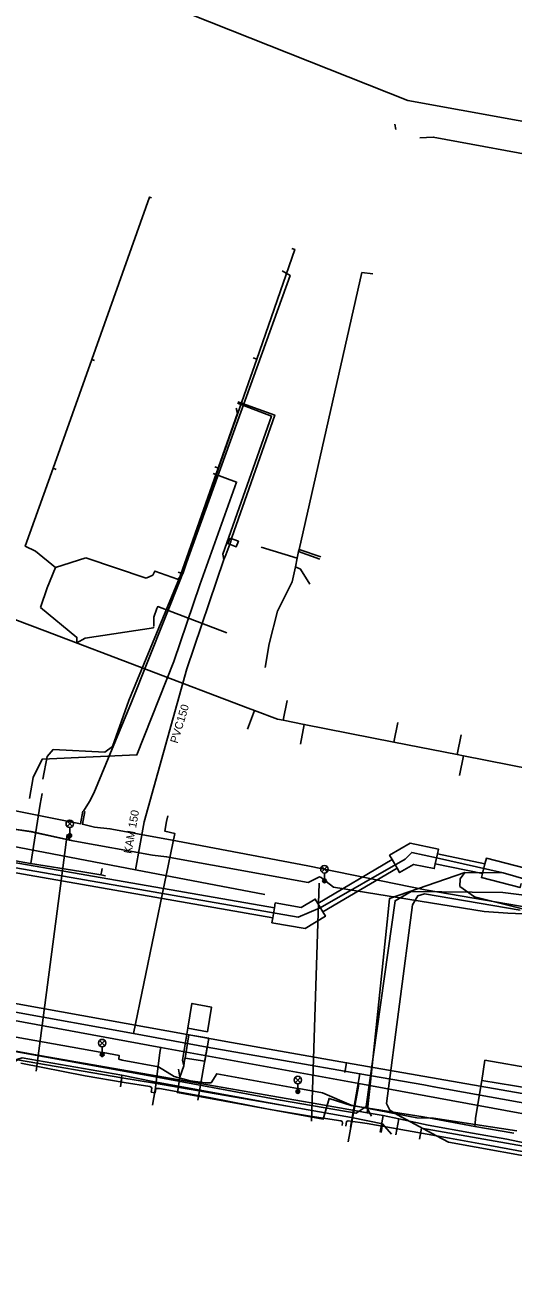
# Model space of a CAD drawing. Extents: x -596228 to -595156, y -1161235 to -1159373.
# Drawn here: x -595977.9 to -595929.1, y -1160338.7 to -1160214.5 of the extents above; entities that cross this region are included whole.
import ezdxf

# ---------------------------------------------------------------- set-up
doc = ezdxf.new("R2010")
doc.units = 0
for name, color, linetype in [('Vrstva 1', 7, 'Continuous'), ('Vrstva 10', 7, 'Continuous'), ('Vrstva 12', 7, 'Continuous'), ('Vrstva 13', 7, 'Continuous'), ('Vrstva 14', 7, 'Continuous'), ('Vrstva 16', 7, 'Continuous'), ('Vrstva 33', 7, 'Continuous'), ('Vrstva 42', 7, 'Continuous'), ('Vrstva 5', 7, 'Continuous'), ('Vrstva 54', 7, 'Continuous'), ('Vrstva 55', 7, 'Continuous'), ('Vrstva 58', 7, 'Continuous'), ('Vrstva 8', 7, 'Continuous'), ('Vrstva 9', 7, 'Continuous')]:
    doc.layers.add(name, color=color, linetype=linetype)

msp = doc.modelspace()

# ---------------------------------------------------------------- linework, layer by layer
at = {"layer": 'Vrstva 1'}
for p, q in [((-595940.938, -1160224.416), (-595940.817, -1160224.964)), ((-595940.938, -1160224.416), (-595940.817, -1160224.964)), ((-595940.938, -1160224.416), (-595940.817, -1160224.964)), ((-595965.453, -1160231.707), (-595965.257, -1160231.788)), ((-595944.225, -1160239.242), (-595950.502, -1160266.906)), ((-595943.129, -1160239.366), (-595944.225, -1160239.242)), ((-595970.953, -1160248.023), (-595971.225, -1160247.927)), ((-595955.08, -1160247.774), (-595954.732, -1160247.91)), ((-595974.774, -1160258.917), (-595975.096, -1160258.804)), ((-595958.907, -1160258.671), (-595958.552, -1160258.79)), ((-595974.851, -1160268.702), (-595976.86, -1160267.085)), ((-595954.288, -1160266.702), (-595950.691, -1160267.797)), ((-595948.335, -1160267.637), (-595950.502, -1160266.906)), ((-595974.851, -1160268.702), (-595971.799, -1160267.755)), ((-595971.799, -1160267.755), (-595965.797, -1160269.776)), ((-595948.413, -1160267.881), (-595950.551, -1160267.132)), ((-595975.683, -1160270.766), (-595974.851, -1160268.702)), ((-595965.797, -1160269.776), (-595965.117, -1160269.499)), ((-595965.117, -1160269.499), (-595964.958, -1160269.155)), ((-595962.598, -1160269.183), (-595962.133, -1160269.335)), ((-595976.35, -1160272.725), (-595975.683, -1160270.766)), ((-595951.191, -1160270.155), (-595952.648, -1160273.078)), ((-595965.013, -1160273.678), (-595964.708, -1160272.831)), ((-595952.648, -1160273.078), (-595953.493, -1160276.354)), ((-595965.017, -1160274.589), (-595965.013, -1160273.678)), ((-595965.037, -1160274.65), (-595965.065, -1160274.732)), ((-595953.493, -1160276.354), (-595953.879, -1160278.709)), ((-595955.666, -1160284.865), (-595954.957, -1160282.995)), ((-595951.692, -1160282.021), (-595952.078, -1160283.983)), ((-595950.375, -1160286.356), (-595949.988, -1160284.394)), ((-595940.634, -1160284.199), (-595941.02, -1160286.161)), ((-595934.315, -1160285.443), (-595934.702, -1160287.405)), ((-595934.45, -1160289.493), (-595934.064, -1160287.531))]:
    msp.add_line(p, q, dxfattribs=at)
for points in [[(-595912.502, -1160230.231), (-595937.093, -1160225.712), (-595938.437, -1160225.792)], [(-595976.86, -1160267.085), (-595977.87, -1160266.599), (-595975.096, -1160258.804), (-595971.225, -1160247.927), (-595965.453, -1160231.707), (-595965.257, -1160231.788)], [(-595964.958, -1160269.155), (-595964.919, -1160269.071), (-595962.659, -1160269.89), (-595962.133, -1160269.335), (-595958.552, -1160258.79), (-595954.732, -1160247.91), (-595950.936, -1160236.932), (-595951.239, -1160236.837)], [(-595956.671, -1160252.305), (-595953.26, -1160253.581), (-595958.13, -1160267.386), (-595958.022, -1160267.926)], [(-595952.65, -1160283.87), (-595954.957, -1160282.995), (-595955.58, -1160282.758), (-595975.9, -1160275.05), (-595978.902, -1160273.911), (-595985.549, -1160271.389), (-595989.355, -1160269.945), (-595993.328, -1160268.438), (-595993.749, -1160268.278), (-595994.45, -1160268.012), (-595998.91, -1160266.32)], [(-595950.502, -1160266.906), (-595950.551, -1160267.132), (-595950.691, -1160267.797), (-595950.874, -1160268.658), (-595951.191, -1160270.155)], [(-595949.415, -1160270.376), (-595950.349, -1160268.887), (-595950.874, -1160268.658)], [(-595976.35, -1160272.725), (-595972.702, -1160275.701), (-595972.715, -1160276.258)], [(-595964.708, -1160272.831), (-595964.621, -1160272.632), (-595957.729, -1160275.25)], [(-595965.065, -1160274.732), (-595971.872, -1160275.766), (-595972.715, -1160276.258)], [(-595909.29, -1160292.41), (-595911.144, -1160292.045), (-595918.081, -1160290.678), (-595918.179, -1160290.659), (-595934.064, -1160287.531), (-595934.702, -1160287.405), (-595941.02, -1160286.161), (-595949.988, -1160284.394), (-595952.078, -1160283.983), (-595952.65, -1160283.87)]]:
    msp.add_lwpolyline(points, dxfattribs=at)
at = {"layer": 'Vrstva 10'}
for p, q in [((-596048.34, -1160286.09), (-595952.97, -1160302.73)), ((-596048.34, -1160286.09), (-595952.97, -1160302.73)), ((-596048.51, -1160287.07), (-595953.14, -1160303.72)), ((-596048.51, -1160287.07), (-595953.14, -1160303.72)), ((-595941.21, -1160297.9), (-595948.63, -1160302.28)), ((-595941.21, -1160297.9), (-595948.63, -1160302.28)), ((-595941.21, -1160297.9), (-595940.7, -1160298.76)), ((-595941.21, -1160297.9), (-595940.7, -1160298.76)), ((-595936.68, -1160297.34), (-595936.89, -1160298.32)), ((-595936.68, -1160297.34), (-595936.89, -1160298.32)), ((-595936.68, -1160297.34), (-595931.93, -1160298.34)), ((-595936.68, -1160297.34), (-595931.93, -1160298.34)), ((-595940.7, -1160298.76), (-595948.12, -1160303.14)), ((-595940.7, -1160298.76), (-595948.12, -1160303.14)), ((-595936.89, -1160298.32), (-595932.18, -1160299.31)), ((-595936.89, -1160298.32), (-595932.18, -1160299.31)), ((-595931.93, -1160298.34), (-595932.18, -1160299.31)), ((-595931.93, -1160298.34), (-595932.18, -1160299.31)), ((-595952.97, -1160302.73), (-595953.14, -1160303.72)), ((-595952.97, -1160302.73), (-595953.14, -1160303.72)), ((-595948.63, -1160302.28), (-595948.12, -1160303.14)), ((-595948.63, -1160302.28), (-595948.12, -1160303.14))]:
    msp.add_line(p, q, dxfattribs=at)
for points in [[(-595941.21, -1160297.9), (-595941.46, -1160297.47), (-595939.41, -1160296.26), (-595936.58, -1160296.85), (-595936.68, -1160297.34)], [(-595941.21, -1160297.9), (-595941.46, -1160297.47), (-595939.41, -1160296.26), (-595936.58, -1160296.85), (-595936.68, -1160297.34)], [(-595931.93, -1160298.34), (-595931.78, -1160297.77), (-595927.91, -1160298.77), (-595928.05, -1160299.31)], [(-595931.93, -1160298.34), (-595931.78, -1160297.77), (-595927.91, -1160298.77), (-595928.05, -1160299.31)], [(-595936.89, -1160298.32), (-595936.99, -1160298.81), (-595939.06, -1160298.38), (-595940.45, -1160299.2), (-595940.7, -1160298.76)], [(-595936.89, -1160298.32), (-595936.99, -1160298.81), (-595939.06, -1160298.38), (-595940.45, -1160299.2), (-595940.7, -1160298.76)], [(-595928.3, -1160300.28), (-595928.41, -1160300.71), (-595932.28, -1160299.7), (-595932.18, -1160299.31)], [(-595928.3, -1160300.28), (-595928.41, -1160300.71), (-595932.28, -1160299.7), (-595932.18, -1160299.31)], [(-595952.97, -1160302.73), (-595952.89, -1160302.24), (-595950.29, -1160302.68), (-595948.88, -1160301.85), (-595948.63, -1160302.28)], [(-595952.97, -1160302.73), (-595952.89, -1160302.24), (-595950.29, -1160302.68), (-595948.88, -1160301.85), (-595948.63, -1160302.28)], [(-595948.12, -1160303.14), (-595947.87, -1160303.57), (-595949.9, -1160304.78), (-595953.22, -1160304.21), (-595953.14, -1160303.72)], [(-595948.12, -1160303.14), (-595947.87, -1160303.57), (-595949.9, -1160304.78), (-595953.22, -1160304.21), (-595953.14, -1160303.72)]]:
    msp.add_lwpolyline(points, dxfattribs=at)
at = {"layer": 'Vrstva 12'}
for p, q in [((-595933.92, -1160299.18), (-595930.09, -1160299.24)), ((-595968.23, -1160319.71), (-595968.36, -1160320.6)), ((-595949.09, -1160322.25), (-595950.27, -1160322.04)), ((-595940.54, -1160323.82), (-595940.82, -1160325.42)), ((-595937.61, -1160324.46), (-595940.54, -1160323.82)), ((-595942.16, -1160324.31), (-595942.31, -1160325.16)), ((-595942.16, -1160324.31), (-595941.25, -1160325.35)), ((-595933.18, -1160325.24), (-595937.61, -1160324.46)), ((-595929.73, -1160325.84), (-595933.18, -1160325.24)), ((-595921.13, -1160327.66), (-595929.73, -1160325.84))]:
    msp.add_line(p, q, dxfattribs=at)
for points in [[(-595906.85, -1160231.25), (-595907.387, -1160230.78), (-595907.31, -1160230.14), (-595906.92, -1160227.97), (-595939.63, -1160222.04), (-595961.4, -1160213.41), (-595962.62, -1160212.93), (-595961.32, -1160205.66)], [(-596051.724, -1160286.477), (-596048.43, -1160286.58), (-595950.59, -1160303.65), (-595948.38, -1160302.71), (-595939.91, -1160297.86), (-595939.24, -1160297.19), (-595936.77, -1160297.74), (-595930.09, -1160299.24)], [(-595916.466, -1160292.479), (-595917.33, -1160296.71), (-595919.49, -1160301.3), (-595921.53, -1160302.54), (-595925, -1160302.02), (-595927.78, -1160302.93), (-595932.98, -1160301.64), (-595934.44, -1160300.59), (-595934.41, -1160299.84), (-595933.92, -1160299.18)], [(-595933.92, -1160299.18), (-595941.47, -1160301.8), (-595941.61, -1160303.16), (-595943.46, -1160321.07), (-595943.68, -1160323.2)], [(-595930.09, -1160299.24), (-595889.94, -1160310.85), (-595809.314, -1160322.217)], [(-595993.27, -1160315.38), (-595985.71, -1160316.88), (-595979.31, -1160318.37), (-595978.65, -1160317.92), (-595968.23, -1160319.71)], [(-595950.27, -1160322.04), (-595977, -1160317.37), (-595992.24, -1160314.56)], [(-595968.23, -1160319.71), (-595965.16, -1160320.23), (-595951.67, -1160322.53), (-595945.25, -1160323.67), (-595942.16, -1160324.31)], [(-595943.68, -1160323.2), (-595944.97, -1160322.97), (-595949.09, -1160322.25)], [(-595940.54, -1160323.82), (-595942.11, -1160323.47), (-595943.68, -1160323.2)]]:
    msp.add_lwpolyline(points, dxfattribs=at)
at = {"layer": 'Vrstva 13'}
msp.add_line((-595942.11, -1160323.47), (-595942.4, -1160325.15), dxfattribs=at)
at = {"layer": 'Vrstva 14'}
for p, q in [((-595976.371, -1160292.38), (-595976.186, -1160291.294)), ((-595977.321, -1160298.28), (-595976.371, -1160292.38)), ((-595970.309, -1160299.445), (-595970.261, -1160299.167)), ((-595970.261, -1160299.167), (-595970.196, -1160298.797))]:
    msp.add_line(p, q, dxfattribs=at)
for points in [[(-595976.116, -1160289.874), (-595975.686, -1160287.6), (-595975.087, -1160286.906), (-595969.912, -1160287.158), (-595969.149, -1160286.605), (-595967.521, -1160281.999), (-595962.403, -1160269.578), (-595956.647, -1160253.3), (-595956.797, -1160252.796)], [(-595969.84, -1160299.527), (-595970.309, -1160299.445), (-595972.313, -1160299.096), (-595977.338, -1160298.303), (-596006.513, -1160293.133), (-596016.44, -1160291.405), (-596042.165, -1160286.921), (-596073.176, -1160281.516), (-596075.808, -1160281.057)], [(-595912.327, -1160326.199), (-595944.525, -1160320.296), (-595964.314, -1160316.668), (-595981.5, -1160313.518), (-595993.326, -1160311.35), (-595998.98, -1160310.314), (-596012.243, -1160307.882), (-596018.266, -1160306.788), (-596020.483, -1160306.371), (-596031.546, -1160304.536), (-596031.549, -1160304.535)], [(-595964.314, -1160316.668), (-595964.374, -1160316.996), (-595964.413, -1160317.209), (-595964.893, -1160320.929), (-595965.143, -1160322.456)], [(-595944.525, -1160320.296), (-595944.571, -1160320.544), (-595945.592, -1160326.115)]]:
    msp.add_lwpolyline(points, dxfattribs=at)
at = {"layer": 'Vrstva 16'}
for p, q in [((-595963.75, -1160294.09), (-595963.619, -1160293.53)), ((-595959.68, -1160316.64), (-595960.61, -1160321.96)), ((-595944.42, -1160319.31), (-595945.35, -1160324.63))]:
    msp.add_line(p, q, dxfattribs=at)
for points in [[(-595977.446, -1160291.788), (-595977.072, -1160289.704), (-595976.194, -1160287.882), (-595966.711, -1160287.45), (-595963.033, -1160278.112), (-595960.436, -1160270.448), (-595956.752, -1160260.184), (-595959.101, -1160259.322)], [(-595963.75, -1160294.09), (-595963.904, -1160295.078), (-595962.926, -1160295.287), (-595967.05, -1160315.3)], [(-595917.38, -1160324.14), (-595937.03, -1160320.6), (-595938.02, -1160320.43), (-595944.42, -1160319.31), (-595959.68, -1160316.64), (-595967.05, -1160315.3), (-595979.197, -1160313.085)], [(-595918.06, -1160328.3), (-595938.26, -1160324.76), (-595938.46, -1160325.84)]]:
    msp.add_lwpolyline(points, dxfattribs=at)
at = {"layer": 'Vrstva 33'}
for p, q in [((-595973.687, -1160294.07), (-595973.157, -1160294.6)), ((-595973.687, -1160294.6), (-595973.157, -1160294.07)), ((-595973.422, -1160295.485), (-595973.422, -1160294.71)), ((-595948.231, -1160298.612), (-595947.701, -1160299.142)), ((-595948.231, -1160299.142), (-595947.701, -1160298.612)), ((-595947.966, -1160300.027), (-595947.966, -1160299.252)), ((-595970.446, -1160315.978), (-595969.916, -1160316.508)), ((-595970.446, -1160316.508), (-595969.916, -1160315.978)), ((-595970.181, -1160317.393), (-595970.181, -1160316.618)), ((-595950.893, -1160319.67), (-595950.363, -1160320.2)), ((-595950.893, -1160320.2), (-595950.363, -1160319.67)), ((-595950.628, -1160321.085), (-595950.628, -1160320.31))]:
    msp.add_line(p, q, dxfattribs=at)
for centre, radius in [((-595973.422, -1160294.335), 0.375), ((-595973.422, -1160295.485), 0.19), ((-595973.422, -1160295.485), 0.05), ((-595947.966, -1160298.877), 0.375), ((-595947.966, -1160300.027), 0.19), ((-595947.966, -1160300.027), 0.05), ((-595970.181, -1160316.243), 0.375), ((-595970.181, -1160317.393), 0.19), ((-595970.181, -1160317.393), 0.05), ((-595950.628, -1160319.935), 0.375), ((-595950.628, -1160321.085), 0.19), ((-595950.628, -1160321.085), 0.05)]:
    msp.add_circle(centre, radius, dxfattribs=at)
at = {"layer": 'Vrstva 42'}
for p, q in [((-595962.42, -1160319.656), (-595962.557, -1160318.834)), ((-595943.78, -1160322.58), (-595943.26, -1160323.541))]:
    msp.add_line(p, q, dxfattribs=at)
for points in [[(-595972.038, -1160293.081), (-595971.453, -1160292.114), (-595971.024, -1160291.252), (-595967.238, -1160282.175), (-595962.289, -1160269.728), (-595951.384, -1160239.549), (-595952.196, -1160239.084)], [(-596018.157, -1160284.331), (-596018.382, -1160285.003), (-596018.405, -1160285.405), (-596018.227, -1160285.652), (-596007.964, -1160287.753), (-596007.682, -1160287.573), (-596007.39, -1160286.388), (-596007.188, -1160286.423), (-596006.995, -1160286.461), (-596007.256, -1160287.5), (-596006.983, -1160287.912), (-596006.502, -1160288.072), (-596000.695, -1160288.762), (-595985.352, -1160291.731), (-595972.344, -1160294.329), (-595972.123, -1160293.062)], [(-595971.926, -1160293.096), (-595972.149, -1160294.375), (-595970.95, -1160294.68)], [(-595970.95, -1160294.68), (-595969.41, -1160294.83), (-595963.368, -1160295.921), (-595949.631, -1160298.537), (-595937.889, -1160300.943), (-595928.355, -1160302.554), (-595926.404, -1160302.777), (-595925.807, -1160302.472), (-595922.787, -1160298.86), (-595922.611, -1160298.637), (-595919.917, -1160293.875), (-595919.369, -1160292.663)], [(-596107.81, -1160293.86), (-596090.53, -1160296.67), (-596075.54, -1160299.61), (-596065.471, -1160301.409), (-596051.42, -1160303.91), (-596041.32, -1160306.03), (-596036.8, -1160306.81), (-596029.31, -1160308.02), (-596012.1, -1160311.59), (-595998.15, -1160313.88), (-595982.44, -1160316.45), (-595965.41, -1160319.5), (-595952.36, -1160321.95), (-595944.8, -1160323.25), (-595943.78, -1160322.58)], [(-596107.81, -1160293.86), (-596090.53, -1160296.67), (-596075.54, -1160299.61), (-596065.471, -1160301.409), (-596051.42, -1160303.91), (-596041.32, -1160306.03), (-596036.8, -1160306.81), (-596029.31, -1160308.02), (-596012.1, -1160311.59), (-595998.15, -1160313.88), (-595982.44, -1160316.45), (-595965.41, -1160319.5), (-595952.36, -1160321.95), (-595944.8, -1160323.25), (-595943.78, -1160322.58)], [(-595943.26, -1160323.541), (-595943.78, -1160322.58), (-595940.91, -1160302.02), (-595939.31, -1160301.1), (-595930.15, -1160301.19), (-595925.58, -1160301.75), (-595922.51, -1160298.12), (-595919.61, -1160297.13), (-595916.66, -1160297.13), (-595905.75, -1160297.26), (-595900.08, -1160297.55), (-595895.98, -1160298.37), (-595889.04, -1160301.63), (-595877.87, -1160306.09), (-595875.35, -1160307.92), (-595868.01, -1160309.1), (-595862.33, -1160310.88), (-595847.13, -1160313.44), (-595833.42, -1160315.69)], [(-595943.26, -1160323.541), (-595943.78, -1160322.58), (-595940.91, -1160302.02), (-595939.31, -1160301.1), (-595930.15, -1160301.19), (-595925.58, -1160301.75), (-595922.51, -1160298.12), (-595919.61, -1160297.13), (-595916.66, -1160297.13), (-595905.75, -1160297.26), (-595900.08, -1160297.55), (-595895.98, -1160298.37), (-595889.04, -1160301.63), (-595877.87, -1160306.09), (-595875.35, -1160307.92), (-595868.01, -1160309.1), (-595862.33, -1160310.88), (-595847.13, -1160313.44), (-595833.42, -1160315.69)], [(-595943.26, -1160323.541), (-595943.78, -1160322.58), (-595940.91, -1160302.02), (-595939.31, -1160301.1), (-595930.15, -1160301.19), (-595925.58, -1160301.75), (-595922.51, -1160298.12), (-595919.61, -1160297.13), (-595916.66, -1160297.13), (-595905.75, -1160297.26), (-595900.08, -1160297.55), (-595895.98, -1160298.37), (-595889.04, -1160301.63), (-595877.87, -1160306.09), (-595875.35, -1160307.92), (-595868.01, -1160309.1), (-595862.33, -1160310.88), (-595847.13, -1160313.44), (-595833.42, -1160315.69)], [(-595943.26, -1160323.541), (-595943.78, -1160322.58), (-595940.91, -1160302.02), (-595939.31, -1160301.1), (-595930.15, -1160301.19), (-595925.58, -1160301.75), (-595922.51, -1160298.12), (-595919.61, -1160297.13), (-595916.66, -1160297.13), (-595905.75, -1160297.26), (-595900.08, -1160297.55), (-595895.98, -1160298.37), (-595889.04, -1160301.63), (-595877.87, -1160306.09), (-595875.35, -1160307.92), (-595868.01, -1160309.1), (-595862.33, -1160310.88), (-595847.13, -1160313.44), (-595833.42, -1160315.69)], [(-595943.78, -1160322.58), (-595940.91, -1160302.02), (-595939.31, -1160301.1), (-595930.15, -1160301.19), (-595925.58, -1160301.75), (-595922.51, -1160298.12), (-595919.61, -1160297.13), (-595916.66, -1160297.13), (-595905.75, -1160297.26), (-595900.08, -1160297.55), (-595895.98, -1160298.37), (-595889.04, -1160301.63), (-595877.87, -1160306.09), (-595875.35, -1160307.92), (-595876.03, -1160312.35), (-595876.906, -1160312.977)], [(-595943.78, -1160322.58), (-595940.91, -1160302.02), (-595939.31, -1160301.1), (-595930.15, -1160301.19), (-595925.58, -1160301.75), (-595922.51, -1160298.12), (-595919.61, -1160297.13), (-595916.66, -1160297.13), (-595905.75, -1160297.26), (-595900.08, -1160297.55), (-595895.98, -1160298.37), (-595889.04, -1160301.63), (-595877.87, -1160306.09), (-595875.35, -1160307.92), (-595876.03, -1160312.35), (-595876.906, -1160312.977)], [(-595928.411, -1160302.95), (-595937.955, -1160301.337), (-595938.626, -1160301.525), (-595939.152, -1160302.415), (-595941.778, -1160322.265), (-595941.446, -1160322.93), (-595940.678, -1160323.414), (-595936.771, -1160325.507), (-595935.565, -1160326.153), (-595924.874, -1160328.07)], [(-595962.025, -1160318.531), (-595962.156, -1160317.932), (-595961.629, -1160314.762), (-595959.656, -1160315.105), (-595959.262, -1160312.652), (-595961.205, -1160312.278), (-595961.629, -1160314.762)], [(-595962.025, -1160318.531), (-595961.95, -1160317.961), (-595961.893, -1160317.741), (-595959.92, -1160318.057), (-595959.526, -1160315.756), (-595961.526, -1160315.418), (-595961.893, -1160317.741)], [(-595932.932, -1160324.581), (-595932.885, -1160324.298), (-595932.877, -1160323.754), (-595932.247, -1160319.983), (-595931.921, -1160317.962), (-595926.975, -1160318.829), (-595927.32, -1160320.768), (-595932.247, -1160319.983)], [(-595978.302, -1160318.261), (-595971.867, -1160319.52), (-595967.971, -1160320.174), (-595965.424, -1160320.576), (-595965.279, -1160320.643), (-595965.207, -1160320.749), (-595965.284, -1160321.139), (-595965.086, -1160321.172), (-595964.887, -1160321.213), (-595964.823, -1160320.803), (-595964.714, -1160320.764), (-595964.449, -1160320.782), (-595959.5, -1160321.665), (-595953.394, -1160322.866), (-595949.401, -1160323.543), (-595946.333, -1160324), (-595946.206, -1160324.074), (-595946.161, -1160324.21), (-595946.197, -1160324.479)], [(-595962.025, -1160318.531), (-595962.42, -1160319.656), (-595962.662, -1160321.181), (-595948.08, -1160323.83), (-595947.509, -1160321.773), (-595945.292, -1160322.475), (-595938.108, -1160323.606), (-595932.932, -1160324.581), (-595929.027, -1160325.242)], [(-595945.819, -1160324.546), (-595945.748, -1160324.061), (-595945.592, -1160324.019), (-595943.697, -1160324.265), (-595936.771, -1160325.507), (-595935.472, -1160325.74), (-595931.446, -1160326.474), (-595924.764, -1160327.692), (-595923.765, -1160327.878), (-595922.887, -1160328.25), (-595922.352, -1160328.96), (-595922.237, -1160329.564), (-595922.28, -1160330.732), (-595923.313, -1160334.991), (-595923.924, -1160338.282), (-595924.007, -1160338.558), (-595924.133, -1160338.73), (-595924.561, -1160338.655)]]:
    msp.add_lwpolyline(points, dxfattribs=at)
at = {"layer": 'Vrstva 5'}
for p, q in [((-595957.837, -1160267.437), (-595957.335, -1160266.122)), ((-595957.837, -1160267.437), (-595957.335, -1160266.122)), ((-595961.721, -1160278.852), (-595958.022, -1160267.926)), ((-595961.721, -1160278.852), (-595958.022, -1160267.926)), ((-595958.022, -1160267.926), (-595957.837, -1160267.437)), ((-595958.022, -1160267.926), (-595957.837, -1160267.437)), ((-595966, -1160294.14), (-595966.838, -1160298.929))]:
    msp.add_line(p, q, dxfattribs=at)
for points in [[(-595957.208, -1160265.729), (-595952.928, -1160253.49), (-595956.621, -1160252.16)], [(-595957.208, -1160265.729), (-595952.928, -1160253.49), (-595956.621, -1160252.16)], [(-595958.022, -1160267.926), (-595958.13, -1160267.386), (-595953.26, -1160253.581), (-595956.671, -1160252.305)], [(-595958.022, -1160267.926), (-595958.13, -1160267.386), (-595953.26, -1160253.581), (-595956.671, -1160252.305)], [(-595957.403, -1160265.776), (-595956.566, -1160266.087), (-595956.774, -1160266.647), (-595957.611, -1160266.336), (-595957.403, -1160265.776)], [(-595957.335, -1160266.122), (-595957.209, -1160265.732), (-595957.208, -1160265.729)], [(-595957.335, -1160266.122), (-595957.209, -1160265.732), (-595957.208, -1160265.729)], [(-595961.721, -1160278.852), (-595966, -1160294.14), (-595966.838, -1160298.929)]]:
    msp.add_lwpolyline(points, dxfattribs=at)
at = {"layer": 'Vrstva 54'}
for p, q in [((-595974.25, -1160299.77), (-595973.67, -1160295.4)), ((-595976.79, -1160319.05), (-595974.25, -1160299.77)), ((-595948.62, -1160304.276), (-595948.49, -1160300.26)), ((-595949.26, -1160324.06), (-595948.62, -1160304.28)), ((-595948.62, -1160304.276), (-595948.62, -1160304.28))]:
    msp.add_line(p, q, dxfattribs=at)
at = {"layer": 'Vrstva 55'}
for points in [[(-595979.66, -1160294.77), (-595977.28, -1160295.12), (-595973.583, -1160295.924), (-595973.498, -1160295.541), (-595973.41, -1160295.42), (-595973.381, -1160295.567), (-595973.466, -1160295.949), (-595972.91, -1160296.07), (-595965.15, -1160297.47), (-595963.75, -1160297.62), (-595949.58, -1160300.18), (-595948.47, -1160299.63), (-595948.3, -1160299.69), (-595947.94, -1160300.03), (-595947.79, -1160300.11), (-595947.06, -1160300.66), (-595932.01, -1160303.09), (-595929.63, -1160303.27), (-595925.74, -1160303.44)], [(-595981.61, -1160315.14), (-595970.37, -1160317.14), (-595970.187, -1160317.172), (-595970.16, -1160317.4), (-595970.069, -1160317.193), (-595968.5, -1160317.47), (-595968.51, -1160317.86), (-595968.18, -1160317.94), (-595964.54, -1160318.61), (-595963, -1160319.59), (-595961.38, -1160320.01), (-595959.85, -1160320.2), (-595959.3, -1160320.22), (-595958.73, -1160319.3), (-595950.645, -1160320.767), (-595950.692, -1160320.96), (-595950.66, -1160321.08), (-595950.576, -1160320.988), (-595950.527, -1160320.789), (-595948.15, -1160321.22), (-595945.29, -1160322.44), (-595938.74, -1160323.71), (-595937.08, -1160323.76), (-595928.74, -1160325.02)]]:
    msp.add_lwpolyline(points, dxfattribs=at)
at = {"layer": 'Vrstva 58'}
for p, q in [((-595968.21, -1160319.46), (-595968.33, -1160320.42)), ((-595942.16, -1160324.31), (-595942.3, -1160325.11)), ((-595942.16, -1160324.31), (-595941.3, -1160325.29))]:
    msp.add_line(p, q, dxfattribs=at)
for points in [[(-595925.74, -1160303.44), (-595929.63, -1160303.27), (-595932.01, -1160303.09), (-595947.06, -1160300.66), (-595947.79, -1160300.11), (-595948.3, -1160299.69), (-595948.47, -1160299.63), (-595949.58, -1160300.18), (-595963.76, -1160297.62), (-595965.15, -1160297.47), (-595972.91, -1160296.07), (-595977.29, -1160295.11), (-595979.66, -1160294.77)], [(-595993.27, -1160315.38), (-595985.71, -1160316.88), (-595979.25, -1160318.06), (-595978.19, -1160317.72), (-595968.21, -1160319.46)], [(-595968.21, -1160319.46), (-595965.13, -1160320.09), (-595951.67, -1160322.53), (-595945.25, -1160323.67), (-595942.16, -1160324.31)]]:
    msp.add_lwpolyline(points, dxfattribs=at)
at = {"layer": 'Vrstva 9'}
for p, q in [((-595957.25, -1160316.19), (-595998.09, -1160308.81)), ((-595945.929, -1160319.187), (-595945.757, -1160318.202))]:
    msp.add_line(p, q, dxfattribs=at)
for points in [[(-595953.91, -1160301.41), (-595966.838, -1160298.929), (-595995, -1160293.53)], [(-595921.15, -1160322.51), (-595945.757, -1160318.202), (-595957.25, -1160316.19)]]:
    msp.add_lwpolyline(points, dxfattribs=at)

# ---------------------------------------------------------------- texts
at = {"layer": 'Vrstva 8'}
for s, rotation, p in [('PVC150', 73, (-595962.649, -1160286.349)), ('KAM 150', 80, (-595967.252, -1160297.364))]:
    msp.add_text(s, height=0.8, rotation=rotation, dxfattribs=at).set_placement(p)

doc.saveas('drawing.dxf')
